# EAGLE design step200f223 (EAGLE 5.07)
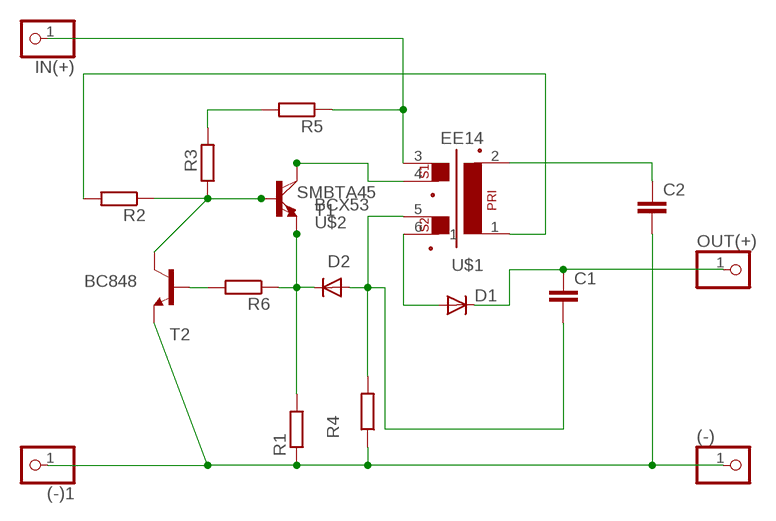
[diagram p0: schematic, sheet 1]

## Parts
(-)  PINHD-1X11MM6  [1X1MM8]
(-)1  PINHD-1X11MM6  [1X1MM8]
C1  C-EU025-025X050  [C025-025X050]
C2  C-EUC0805  [C0805]
D1  DIODE-SMA-DO214  [SMA-DO214AC]
D2  DIODE-MINIMELF  [MINIMELF]
IN(+)  PINHD-1X11MM6  [1X1MM8]
OUT(+)  PINHD-1X11MM6  [1X1MM8]
R1  R-EU_R1206  [R1206]
R2  R-EU_R0805  [R0805]
R3  R-EU_R1206  [R1206]
R4  R-EU_R0805  [R0805]
R5  R-EU_R1206  [R1206]
R6  R-EU_R0805  [R0805]
T1  SMBTA45  BC848  [SOT23]
T2  BC848  [SOT23]
U$1  EE14  [EE14]
U$2  BCX53  [SOT223]

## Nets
A: D1.A U$1.6
B1C2: R2.1 R3.1 T1.B T2.C U$2.1(B)
C1: T1.C U$1.4 U$2.2(C)
EB: D2.C R1.2 R6.1 T1.E U$2.3(E)
N$1: R3.2 R5.2
N$2: R6.2 T2.B
N$4: R2.2 U$1.1
N$6: C2.1 U$1.2
NDOT: C1.2 D2.A R4.2 U$1.5
V+: IN(+).1 R5.1 U$1.3
V-: (-)1.1 (-).1 C2.2 R1.1 R4.1 T2.E
VOUT+: C1.1 D1.K(C) OUT(+).1

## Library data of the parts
(-) (-)1 IN(+) OUT(+) = pinhead:PINHD-1X1: PIN HEADER
C1 C2 = rcl:C-EU: CAPACITOR, European symbol
D1 D2 = diode:DIODE-: DIODE
R1-R6 = rcl:R-EU_: RESISTOR, European symbol
T1 T2 = transistor:BC848: NPN TRANSISTOR
U$1 = trafo:EE14
U$2 = transistor-power:BCX53

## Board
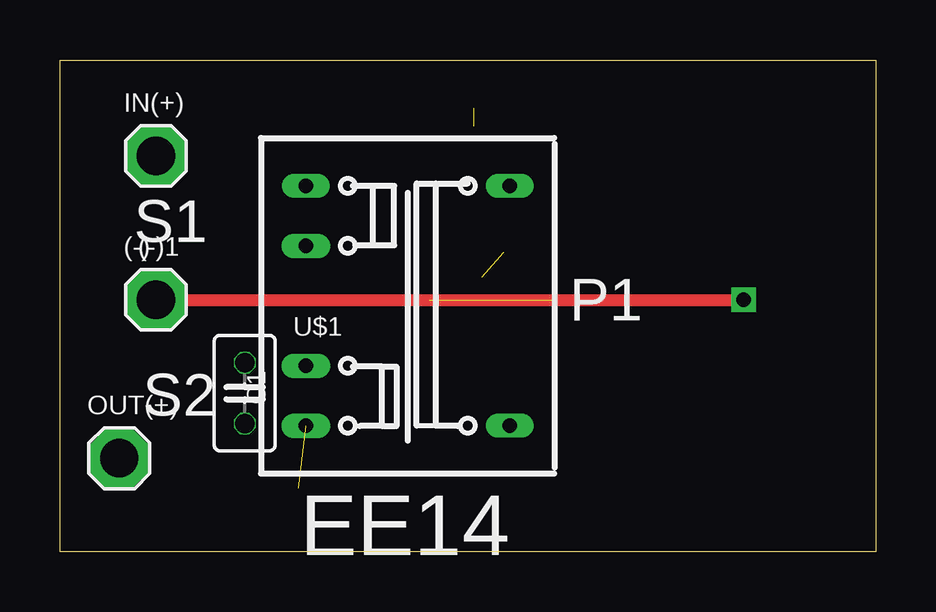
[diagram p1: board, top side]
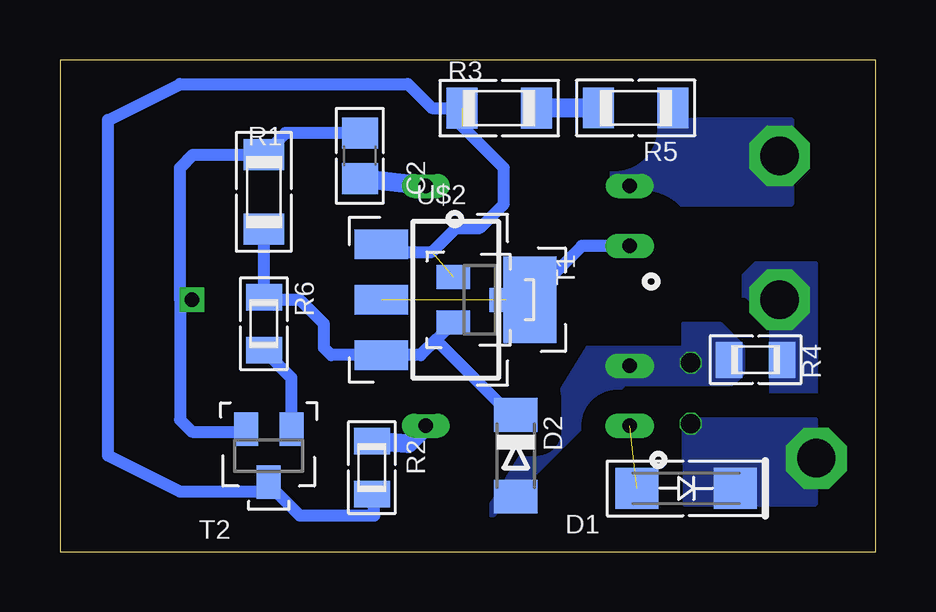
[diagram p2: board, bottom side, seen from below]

Size 34 x 20.5 mm. Coordinates in mm from the lower left corner, seen from the top.
Outline: 0,20.5 34,20.5 34,0 0,0 0,20.5
Copper layers (1*16): Top 0.035mm / dielectric 1.5mm / Bottom 0.035mm
Design rules "default": minimum track width 10mil, minimum drill 20mil, track to track 8mil, track to pad 8mil, pad to pad 8mil, via to via 8mil, smd to smd 8mil, copper to edge 40mil, drill to drill 8mil, minimum pad ring 1mil, minimum via ring 8mil, stop-mask expansion 4mil, vias tented up to drill 0mil, thermal gap 10mil

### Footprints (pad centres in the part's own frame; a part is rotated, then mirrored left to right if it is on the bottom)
1X1MM8 = drill 1.6 pad 2.54 octagon: 1 0,0
C025-025X050 = drill 0.813 octagon: 1 -1.27,0; 2 1.27,0
C0805 = smd 1.3 x 1.5: 1 -0.95,0; 2 0.95,0
SMA-DO214AC = smd 1.8 x 1.7: A 2.05,-0.127; K -2.05,-0.127
MINIMELF = smd 1.4 x 1.8: A 1.7,0; C -1.7,0
R1206 = smd 1.3 x 1.7: 1 -1.55,0; 2 1.55,0
R0805 = smd 1.1 x 1.5: 1 -1.1,0; 2 1.1,0
SOT23 = smd 1 x 1.4: B -0.95,-1.1; C 0,1.1; E 0.95,-1.1
EE14 = drill 0.6 pad 1 long: 1 4.25,-5; 2 4.25,5; 3 -4.25,5 | drill 0.6 pad 1.016 long: 4 -4.25,2.5; 5 -4.25,-2.5; 6 -4.25,-5
SOT223 = smd 1.219 x 2.235: 1 -2.311,-3.099; 2 0,-3.099; 3 2.311,-3.099 | smd 3.6 x 2.2: 4 0,3.099

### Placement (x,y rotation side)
(-)  4,10.5 0 top
(-)1  4,10.5 0 top
C1  7.7,6.61 90 top
C2  21.5,16.5 90 bottom
D1  7.89,2.51 180 bottom
D2  15,4 270 bottom
IN(+)  4,16.5 0 top
OUT(+)  2.47,3.89 0 top
R1  25.5,15 270 bottom
R2  21,3.5 90 bottom
R3  15.69,18.49 0 bottom
R4  5,8 180 bottom
R5  10,18.5 180 bottom
R6  25.5,9.5 270 bottom
T1  16.5,10.5 270 bottom
T2  25.3,4 180 bottom
U$1  14.5,10.25 0 top
U$2  17.5,10.5 270 bottom

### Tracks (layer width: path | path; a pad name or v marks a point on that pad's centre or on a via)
A  (1 unrouted)
B1C2  (2 unrouted)
  Bottom 0.5: 17.24,17.74 15.5,16 15.5,14.5 16.5,13.5 17.5,13.5 18.5,12.5 20.29,12.5 U$2.1 | R3.1 18.49,18.49 19.5,19.5 29,19.5 32,18 32,4 29,2.5 25.7,2.5 T2.C 25.3,2.8 24,1.5 20.9,1.5 R2.1
C1  (1 unrouted)
  Bottom 0.5: U$1.4 12.25,12.75 14.5,10.5 T1.C
EB
  Bottom 0.5: R6.1 25.5,10.5 | R6.1 R1.2 | R6.1 25.4,10.5 24,10.5 23,9.5 23,8.5 22.69,8.19 U$2.3 18.96,8.19 18.32,8.82 | 18.32,8.82 T1.E | D2.C 15.2,5.7 18.32,8.82
N$1
  Bottom 0.8: R5.2 13.13,18.5 R3.2
N$2
  Bottom 0.5: T2.B 24.35,7.25 R6.2
N$4
  Bottom 0.8: R2.2 19.5,4.5 U$1.1
N$6
  Bottom 0.8: U$1.2 C2.1
NDOT
  pour Bottom (isolate 1, rank 3, no thermals): 5.5,8.5 5.5,7.5 6,7 10.5,7 16,1.5 16,2 12,8.5 8,8.5 8,9.5 6.5,9.5
V+
  pour Bottom (isolate 1.8, rank 4, no thermals): 3.5,18 7.5,18 9.6,17.9 10.6,17.4 11,17 11,14.5 3.5,14.5
V-  (via drill 0.6)
  Top 0.5: (-).1 v28.5,10.5
  Bottom 0.5: 29,10.5 29,5.5 28.5,5 26.35,5 T2.E | 29,10.5 29,16 28.45,16.55 R1.1 24.6,17.45 C2.2 | v28.5,10.5 29,10.5
  pour Bottom (isolate 1, rank 4, no thermals): 2.5,12 5,12 5.5,11.5 5.5,10 4.5,9 4.5,6.5 2.5,6.5
VOUT+
  pour Bottom (isolate 1, rank 3, no thermals): 2.5,5.5 7.5,5.5 8,5 8,2 2.5,2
